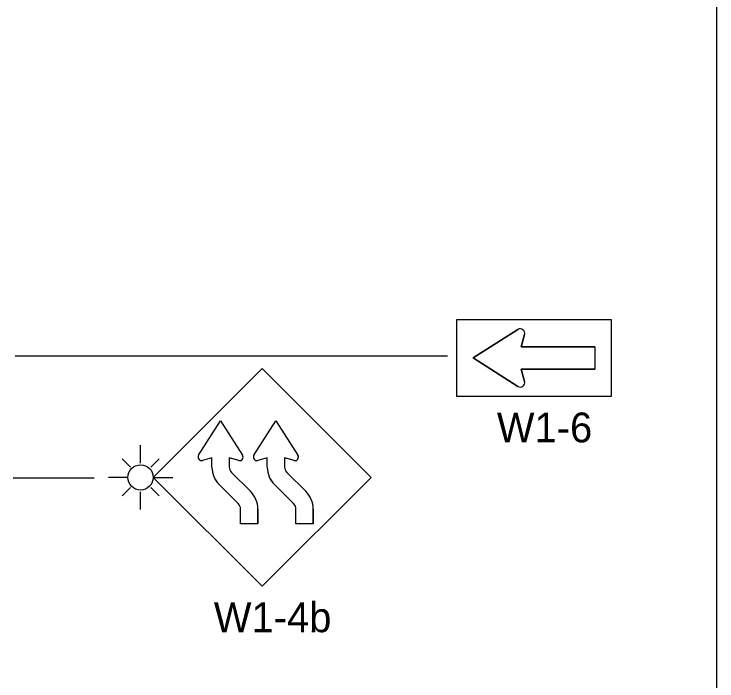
# Model space of a CAD drawing. Extents: x 16723 to 18475, y 7015 to 8267.
# Drawn here: x 17247.5 to 17422.8, y 7602.8 to 7769.1 of the extents above; entities that cross this region are included whole.
import ezdxf

# ---------------------------------------------------------------- set-up
doc = ezdxf.new("R2010")
doc.units = 0
for name, color, linetype in [('BORDER', 7, 'Continuous'), ('TRAFFIC_SIGNS_PR', 7, 'Continuous'), ('TYPICAL_TEXT_DIMEN_PR', 7, 'Continuous')]:
    doc.layers.add(name, color=color, linetype=linetype)

msp = doc.modelspace()

# ---------------------------------------------------------------- linework, layer by layer
at = {"layer": 'BORDER'}
msp.add_line((17422.75, 7216.25), (17422.75, 8216.25), dxfattribs=at)
at = {"layer": 'TRAFFIC_SIGNS_PR'}
for p, q in [((17373.11, 7690.43), (17361.95, 7683.32)), ((17373.95, 7686.12), (17374.79, 7689.18)), ((17392.35, 7686.12), (17373.95, 7686.12)), ((17392.35, 7686.12), (17392.35, 7680.52)), ((17361.95, 7683.32), (17373.11, 7676.22)), ((17282.24, 7653.55), (17309.39, 7680.7)), ((17309.39, 7680.7), (17336.54, 7653.55)), ((17374.79, 7677.46), (17373.95, 7680.52)), ((17373.95, 7680.52), (17392.35, 7680.52)), ((17279.08, 7657.1), (17279.08, 7661.61)), ((17276.57, 7656.06), (17274.46, 7658.17)), ((17281.6, 7656.06), (17283.71, 7658.17)), ((17306.46, 7650.08), (17301.75, 7654.8)), ((17301.75, 7654.8), (17306.46, 7650.08)), ((17320.26, 7650.08), (17315.54, 7654.8)), ((17315.54, 7654.8), (17320.26, 7650.08)), ((17275.93, 7653.55), (17271.09, 7653.55)), ((17282.24, 7653.55), (17287.12, 7653.55)), ((17309.39, 7626.4), (17282.24, 7653.55)), ((17336.54, 7653.55), (17309.39, 7626.4)), ((17303.41, 7647.03), (17298.7, 7651.75)), ((17303.41, 7647.03), (17298.7, 7651.75)), ((17317.21, 7647.03), (17312.49, 7651.75)), ((17317.2, 7647.03), (17312.49, 7651.75)), ((17276.57, 7651.04), (17274.46, 7648.93)), ((17279.08, 7645.58), (17279.08, 7649.99)), ((17281.6, 7651.04), (17283.7, 7648.93)), ((17304.01, 7641.96), (17304.01, 7645.66)), ((17308.33, 7641.96), (17308.33, 7645.66)), ((17317.81, 7641.96), (17317.81, 7645.66)), ((17322.12, 7641.96), (17322.12, 7645.66)), ((17308.33, 7641.96), (17304.01, 7641.96)), ((17322.12, 7641.96), (17317.81, 7641.96))]:
    msp.add_line(p, q, dxfattribs=at)
msp.add_lwpolyline([(17396.35, 7673.72), (17357.95, 7673.72), (17357.95, 7692.92), (17396.35, 7692.92)], close=True, dxfattribs=at)
for points in [[(17373.11, 7676.22), (17361.95, 7683.32), (17373.11, 7690.43)], [(17374.79, 7689.18), (17373.95, 7686.12), (17392.35, 7686.12), (17392.35, 7680.52), (17373.95, 7680.52), (17374.79, 7677.46)], [(17293.54, 7659.07), (17299.02, 7667.68), (17304.5, 7659.07)], [(17293.54, 7659.07), (17299.02, 7667.68), (17304.5, 7659.07)], [(17307.34, 7659.07), (17312.82, 7667.68), (17318.3, 7659.07)], [(17307.34, 7659.07), (17312.82, 7667.68), (17318.3, 7659.07)], [(17296.87, 7656.06), (17296.87, 7658.42), (17294.5, 7657.77)], [(17296.87, 7656.06), (17296.87, 7658.42), (17294.5, 7657.77)], [(17303.54, 7657.77), (17301.18, 7658.42), (17301.19, 7656.13)], [(17303.54, 7657.77), (17302.71, 7658), (17301.18, 7658.42), (17301.19, 7656.13)], [(17310.67, 7656.06), (17310.66, 7658.42), (17308.3, 7657.77)], [(17310.67, 7656.06), (17310.66, 7658.42), (17308.3, 7657.77)], [(17317.34, 7657.77), (17314.98, 7658.42), (17314.98, 7656.13)], [(17317.34, 7657.77), (17316.51, 7658), (17314.98, 7658.42), (17314.98, 7656.13)], [(17308.33, 7645.66), (17308.33, 7641.96), (17304.01, 7641.96), (17304.01, 7645.66)], [(17322.12, 7645.66), (17322.12, 7641.96), (17317.81, 7641.96), (17317.81, 7645.66)]]:
    msp.add_lwpolyline(points, dxfattribs=at)
msp.add_circle((17279.08, 7653.55), 3.15, dxfattribs=at)
for centre, radius, start, end in [((17373.71, 7689.48), 1.12, 344.6731, 122.4696), ((17373.71, 7689.48), 1.12, 344.6731, 122.4696), ((17373.71, 7677.17), 1.12, 237.5304, 15.3269), ((17373.71, 7677.17), 1.12, 237.5304, 15.3269), ((17294.27, 7658.61), 0.866, 147.7292, 285.3172), ((17294.27, 7658.61), 0.866, 147.7196, 285.3201), ((17284.43, 7664.87), 10.8, 327.5335, 327.5431), ((17303.77, 7658.61), 0.864, 254.6014, 32.4796), ((17303.77, 7658.61), 0.866, 254.6148, 32.4712), ((17308.07, 7658.61), 0.866, 147.7292, 285.3172), ((17308.07, 7658.61), 0.866, 147.7196, 285.3201), ((17298.23, 7664.87), 10.8, 327.5335, 327.5431), ((17317.57, 7658.61), 0.864, 254.6014, 32.4796), ((17317.57, 7658.61), 0.866, 254.6148, 32.4712), ((17297.36, 7647.36), 10.8, 105.3192, 105.32), ((17311.15, 7647.36), 10.8, 105.3192, 105.32), ((17303.04, 7656.12), 6.17, 180.6181, 225.7875), ((17303.04, 7656.12), 6.17, 180.6245, 225.2313), ((17303.04, 7656.12), 1.85, 179.8762, 225.7877), ((17303.04, 7656.12), 1.85, 180, 225.7875), ((17316.83, 7656.12), 6.17, 180.6181, 225.7875), ((17316.83, 7656.12), 6.17, 180.6245, 225.2313), ((17316.83, 7656.12), 1.85, 179.8762, 225.7877), ((17316.83, 7656.12), 1.85, 180, 225.7875), ((17302.16, 7645.66), 6.17, 0, 45.7875), ((17302.16, 7645.66), 6.17, 0, 45.7875), ((17302.16, 7645.66), 6.17, 0, 45.7883), ((17315.96, 7645.66), 6.17, 0, 45.7875), ((17315.96, 7645.66), 6.17, 0, 45.7875), ((17315.96, 7645.66), 6.17, 0, 45.7883), ((17302.16, 7645.66), 1.85, 0, 47.628), ((17302.16, 7645.66), 1.85, 0, 45.7875), ((17315.96, 7645.66), 1.85, 0, 47.628), ((17315.96, 7645.66), 1.85, 0, 45.7875)]:
    msp.add_arc(centre, radius, start, end, dxfattribs=at)
at = {"layer": 'TYPICAL_TEXT_DIMEN_PR'}
for p, q in [((17247.8, 7683.83), (17355.55, 7683.83)), ((17267.51, 7653.36), (17247.29, 7653.36))]:
    msp.add_line(p, q, dxfattribs=at)

# ---------------------------------------------------------------- texts
at = {"layer": 'TRAFFIC_SIGNS_PR'}
for s, p in [('W1-6', (17367.89, 7662.28)), ('W1-4b', (17297.34, 7614.96))]:
    msp.add_text(s, height=7.44, dxfattribs=at).set_placement(p)

doc.saveas('drawing.dxf')
